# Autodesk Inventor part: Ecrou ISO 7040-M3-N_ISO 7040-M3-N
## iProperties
Created: 2011-01
Part Number: Ecrou ISO 7040-M3-N_ISO 7040-M3-N
Document SubType Name: Modeling
Designer: eric
Density: 1 g/cm^3
Mass: 0.0826944 g
Surface Area: 1.53081 cm^2
Volume: 0.0826944 cm^3
Author: eric
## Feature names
1. Base1
